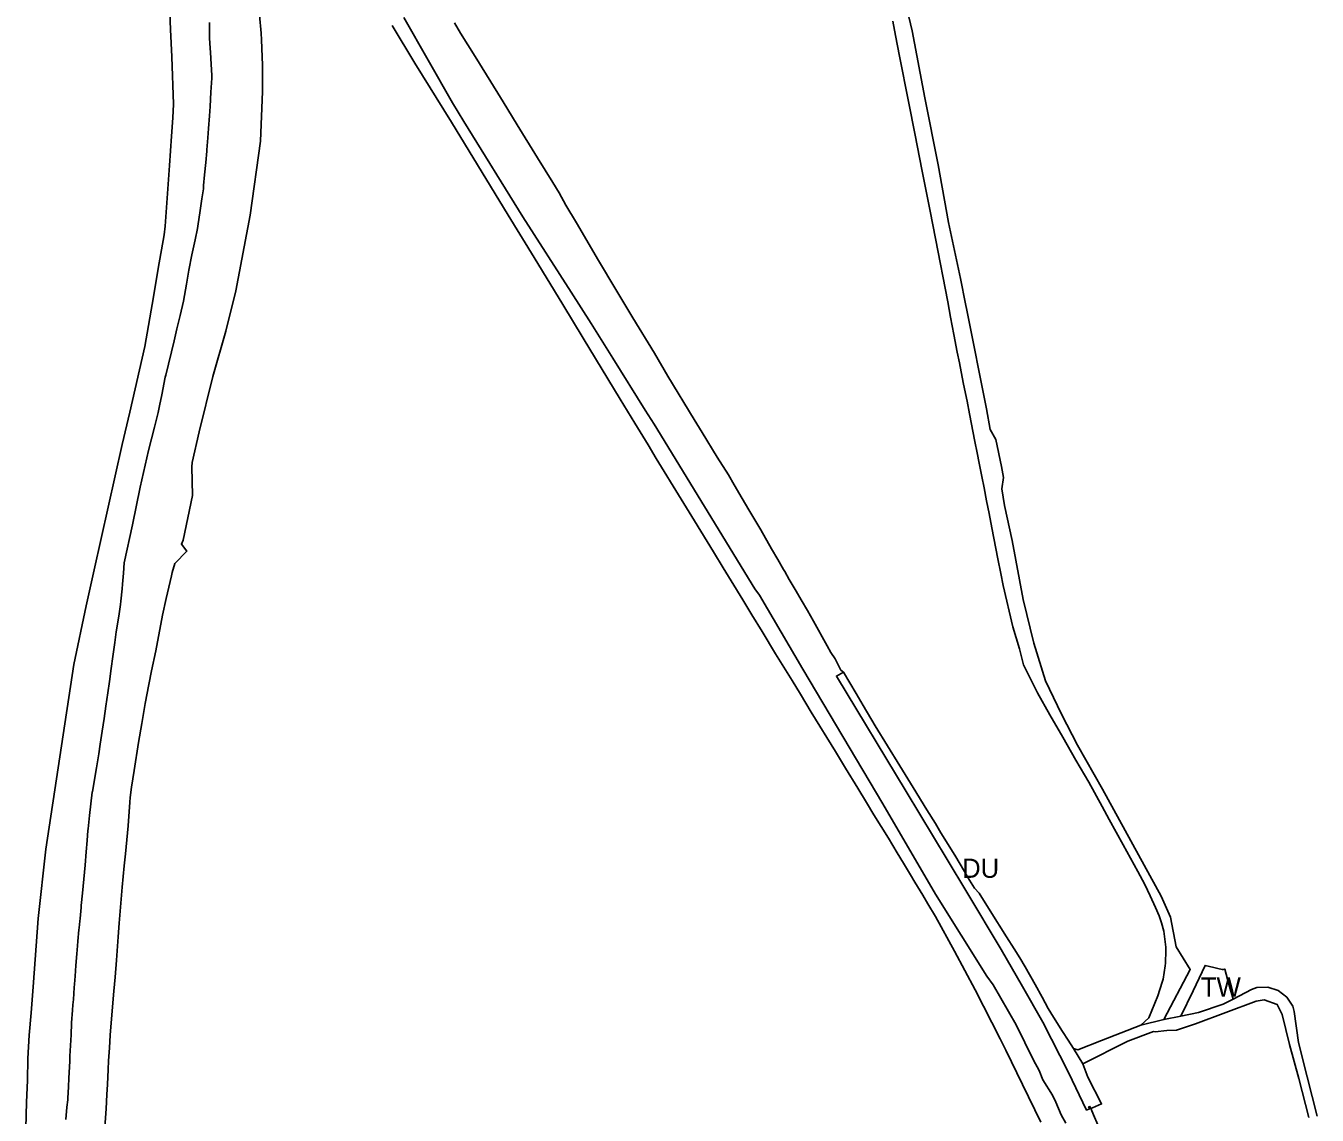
# Model space of a CAD drawing. Extents: x -521047 to -518054, y -1194945 to -1189555.
# Drawn here: x -520853 to -520181, y -1190690 to -1190123 of the extents above; entities that cross this region are included whole.
import ezdxf

# ---------------------------------------------------------------- set-up
doc = ezdxf.new("R2010")
doc.units = 0
for name, color, linetype in [('90310013', 7, 'Continuous'), ('90310023', 7, 'Continuous'), ('90320013', 7, 'Continuous'), ('90390013', 7, 'Continuous')]:
    doc.layers.add(name, color=color, linetype=linetype)

msp = doc.modelspace()

# ---------------------------------------------------------------- linework, layer by layer
at = {"layer": '90310013'}
for points in [[(-520311.54, -1190694.38), (-520313.81, -1190690.05), (-520316.69, -1190683.47), (-520318.39, -1190679.81), (-520323.39, -1190671.81), (-520325.29, -1190666.88), (-520328.39, -1190661.64), (-520337.38, -1190643.13), (-520349.34, -1190622.37), (-520352.61, -1190617.78), (-520379.37, -1190575.04), (-520406.8, -1190528.05), (-520448.49, -1190457.74), (-520471.06, -1190419.32), (-520473.45, -1190415.9), (-520525.96, -1190330.07), (-520530.58, -1190322.93), (-520547.56, -1190295.76), (-520558.81, -1190277.75), (-520569.14, -1190261.44), (-520594.4, -1190222.18), (-520625.12, -1190172.36), (-520630.98, -1190162.68), (-520656.35, -1190118.25)], [(-520662.54, -1190122.49), (-520650.61, -1190142), (-520631.58, -1190172.83), (-520602.03, -1190221.27), (-520588.57, -1190243.38), (-520573.64, -1190267.85), (-520562.95, -1190285.42), (-520543.65, -1190317.19), (-520536, -1190329.69), (-520529.17, -1190340.88), (-520524.85, -1190347.98), (-520511.82, -1190369.31), (-520504.99, -1190380.53), (-520495.11, -1190396.67), (-520489.99, -1190405.05), (-520485.87, -1190411.78), (-520479.82, -1190421.71), (-520475.02, -1190429.58), (-520469.77, -1190438.2), (-520462.71, -1190449.78), (-520454.13, -1190463.8), (-520449.8, -1190470.9), (-520444.12, -1190480.2), (-520431.56, -1190500.75), (-520426.27, -1190509.45), (-520419.93, -1190519.84), (-520415.33, -1190527.35), (-520411.44, -1190533.73), (-520403.94, -1190545.91), (-520399.35, -1190553.5), (-520396.02, -1190558.98), (-520392.43, -1190564.91), (-520390.09, -1190568.79), (-520385.97, -1190575.6), (-520383.32, -1190580.03), (-520379.45, -1190586.67), (-520369.41, -1190604.73), (-520358.66, -1190624.95), (-520345.65, -1190650.45), (-520342.71, -1190656.38), (-520334, -1190674.28), (-520324.46, -1190693.89)], [(-520302.58, -1190663.54), (-520307.46, -1190655.43), (-520310.32, -1190651.11), (-520313.14, -1190646.59), (-520317.05, -1190640.57), (-520319.31, -1190636.97), (-520320.59, -1190634.65), (-520323.87, -1190628.67), (-520327.5, -1190622.06), (-520332.64, -1190612.96), (-520335.39, -1190608.31), (-520338.33, -1190603.61), (-520342.37, -1190597.29), (-520350.92, -1190583.67), (-520356.67, -1190574.53), (-520359.14, -1190572.02), (-520362.5, -1190566.32), (-520364.34, -1190563.2), (-520369.26, -1190554.67), (-520376.52, -1190543.09), (-520379.44, -1190538.17), (-520383.85, -1190531.04), (-520391.01, -1190519.48), (-520397.98, -1190508.23), (-520410.78, -1190487.26), (-520417.03, -1190476.73), (-520420.7, -1190470.58), (-520427.37, -1190459.39), (-520431.02, -1190461.45), (-520394.68, -1190521.61), (-520373.25, -1190557.02), (-520363.08, -1190574.03), (-520345.16, -1190603.9), (-520333.97, -1190623.14), (-520323.53, -1190641.8), (-520310.09, -1190667.94), (-520300.63, -1190687.6), (-520299.19, -1190687), (-520299.58, -1190685.96), (-520298.9, -1190685.67), (-520298.45, -1190686.69), (-520297.57, -1190686.32), (-520292.81, -1190684.4), (-520300.02, -1190670.48), (-520302.58, -1190663.54)], [(-520180.5, -1190690.67), (-520185.7, -1190670.28), (-520190.15, -1190652.41), (-520192.44, -1190636.14), (-520193.15, -1190633.39), (-520196.31, -1190628.66), (-520200.85, -1190625.24), (-520206.24, -1190623.53), (-520211.94, -1190623.66), (-520214.66, -1190624.69), (-520224.31, -1190629.74), (-520229.44, -1190632.43), (-520242.27, -1190636.69), (-520251.47, -1190638.58), (-520260.36, -1190640.4), (-520272.31, -1190643.28), (-520292.86, -1190651.31), (-520305.17, -1190656.12), (-520307.46, -1190655.43), (-520302.58, -1190663.54)], [(-520302.58, -1190663.54), (-520279.12, -1190651.75), (-520265.85, -1190646.71), (-520264.87, -1190646.73), (-520258.89, -1190646.14), (-520253.81, -1190645.91), (-520243.84, -1190642.67), (-520212.3, -1190630.74), (-520208.07, -1190630.09), (-520201.28, -1190632.52), (-520198.74, -1190637.77), (-520194.85, -1190653.37), (-520190.1, -1190671.19), (-520184.89, -1190691.51)]]:
    msp.add_lwpolyline(points, dxfattribs=at)
at = {"layer": '90310023'}
for points in [[(-520778.83, -1190102.4), (-520777.95, -1190124.57), (-520777.29, -1190138.74), (-520776.47, -1190163.36), (-520776.83, -1190170.44), (-520777.49, -1190180.07), (-520778.53, -1190195.44), (-520780.79, -1190226.94), (-520781.3, -1190231.43), (-520784.36, -1190249.11), (-520786.83, -1190263.81), (-520791.44, -1190289.68), (-520799.14, -1190323.82), (-520803.11, -1190340.79), (-520817.75, -1190406.02), (-520822, -1190424.77), (-520828.37, -1190455.3), (-520842.97, -1190551.61), (-520846.95, -1190587.68), (-520849.58, -1190623.3), (-520850.63, -1190636.95), (-520851.64, -1190648.56), (-520852.28, -1190660.73), (-520852.56, -1190672.24), (-520852.94, -1190683.51), (-520853.37, -1190697.08)], [(-520401.68, -1190120.11), (-520400.22, -1190127.57), (-520398.08, -1190138.46), (-520393.44, -1190162.05), (-520389.99, -1190179.56), (-520386.49, -1190197.4), (-520382.22, -1190219.18), (-520379.42, -1190233.48), (-520372.97, -1190266.32), (-520371.58, -1190274.42), (-520369.76, -1190283.42), (-520368, -1190292.59), (-520366.87, -1190298.24), (-520364.88, -1190308.35), (-520363.75, -1190314.16), (-520362.96, -1190318.16), (-520361.67, -1190324.78), (-520358.8, -1190339.19), (-520357.64, -1190345.16), (-520356.65, -1190350.44), (-520356.28, -1190352.2), (-520355.24, -1190357.44), (-520354.1, -1190363.35), (-520352.77, -1190370.15), (-520351.48, -1190376.69), (-520349.98, -1190384.24), (-520346.85, -1190400.25), (-520345.34, -1190407.94), (-520344.11, -1190414.17), (-520339.16, -1190435.68), (-520335.69, -1190447.27), (-520333.6, -1190455.52), (-520326.28, -1190470.19), (-520319.79, -1190481.7), (-520313.06, -1190493.24), (-520306.18, -1190505.19), (-520299.49, -1190516.65), (-520292.56, -1190529.3), (-520288.83, -1190536.11), (-520281.56, -1190549.39), (-520273.96, -1190563.31), (-520270.32, -1190570.06), (-520267.58, -1190575.89), (-520264.82, -1190581.96), (-520262.79, -1190586.33), (-520261.69, -1190589.95), (-520260.46, -1190594.42), (-520260.08, -1190597.14), (-520259.34, -1190602.74), (-520259.34, -1190604.41), (-520259.47, -1190611.1), (-520259.64, -1190612.41), (-520260.77, -1190619.4), (-520261.32, -1190621), (-520263.6, -1190628.04), (-520268.22, -1190639.47), (-520272.31, -1190643.28), (-520260.36, -1190640.4), (-520246.6, -1190614.37), (-520254.03, -1190602.44), (-520256.94, -1190586.97), (-520261.73, -1190576.17), (-520292.37, -1190520.37), (-520305.38, -1190497.4), (-520313.7, -1190481.31), (-520322.01, -1190463.84), (-520328.19, -1190444.19), (-520333.62, -1190421.51), (-520339.48, -1190390.73), (-520343.5, -1190372.52), (-520344.85, -1190363.88), (-520343.97, -1190357.86), (-520345.06, -1190352.29), (-520347.86, -1190338.07), (-520350.9, -1190332.99), (-520352.86, -1190322.18), (-520363.12, -1190270.76), (-520363.78, -1190267.42), (-520366.37, -1190254.23), (-520372.66, -1190225.12), (-520377.99, -1190195.02), (-520384.87, -1190160.07), (-520391.56, -1190125.16), (-520393.2, -1190117.89)], [(-520832.56, -1190692.51), (-520831.92, -1190686.11), (-520831.53, -1190682.22), (-520831.48, -1190681.4), (-520831.18, -1190675.42), (-520830.95, -1190670.95), (-520830.65, -1190664.99), (-520830.5, -1190662.17), (-520830.37, -1190659.51), (-520830.09, -1190653.98), (-520829.81, -1190648.4), (-520829.5, -1190642.29), (-520829.49, -1190642.08), (-520829, -1190635.46), (-520828.79, -1190632.68), (-520828.59, -1190629.93), (-520828.13, -1190623.75), (-520828, -1190622.02), (-520827.69, -1190617.85), (-520827.28, -1190612.32), (-520826.82, -1190606.09), (-520826.51, -1190601.96), (-520826.28, -1190599.56), (-520825.69, -1190593.61), (-520825.59, -1190592.55), (-520825.25, -1190589.08), (-520825.13, -1190587.77), (-520824.56, -1190581.94), (-520824.46, -1190580.91), (-520823.86, -1190574.55), (-520822.46, -1190559.96), (-520821.91, -1190553.06), (-520821.44, -1190547.14), (-520821.02, -1190541.86), (-520820.91, -1190540.94), (-520820.12, -1190534.01), (-520819.44, -1190528.07), (-520818.73, -1190521.84), (-520818.67, -1190521.49), (-520816.62, -1190509.25), (-520815.39, -1190501.97), (-520814.61, -1190496.95), (-520813.56, -1190490.15), (-520812.54, -1190483.57), (-520811.63, -1190477.09), (-520810.65, -1190470.17), (-520809.83, -1190464.32), (-520808.9, -1190457.54), (-520808.05, -1190451.22), (-520807.06, -1190443.91), (-520806.22, -1190438.37), (-520804.98, -1190430.18), (-520804.05, -1190424.07), (-520803.81, -1190422.46), (-520803.25, -1190415.91), (-520803.04, -1190413.49), (-520802.55, -1190407.76), (-520802.08, -1190402.34), (-520797.81, -1190382.66), (-520793.77, -1190363.04), (-520789.51, -1190343.91), (-520786.36, -1190331.78), (-520785.46, -1190328.32), (-520784.38, -1190324.15), (-520783.68, -1190320.65), (-520782.55, -1190314.95), (-520780.71, -1190305.7), (-520780.47, -1190304.54), (-520776.16, -1190286.78), (-520774.67, -1190280.5), (-520773, -1190273.46), (-520771.25, -1190266.04), (-520769.69, -1190257.16), (-520768.43, -1190249.96), (-520766.85, -1190241.85), (-520765.22, -1190234.17), (-520763.96, -1190228.21), (-520763.7, -1190226.98), (-520762.5, -1190218.73), (-520761.63, -1190212.72), (-520760.87, -1190207.48), (-520760.72, -1190205.7), (-520760.23, -1190200.24), (-520759.65, -1190193.81), (-520759.12, -1190187.87), (-520759.06, -1190187.22), (-520758.55, -1190180.97), (-520758.15, -1190176.09), (-520757.6, -1190169.44), (-520757.3, -1190164.53), (-520756.9, -1190157.22), (-520756.5, -1190149.9), (-520756.42, -1190148.49), (-520756.81, -1190142.53), (-520757.19, -1190136.49), (-520757.5, -1190131.72), (-520757.68, -1190128.9), (-520757.7, -1190126.98), (-520757.75, -1190120.86)]]:
    msp.add_lwpolyline(points, dxfattribs=at)
at = {"layer": '90320013'}
for points in [[(-520812.74, -1190703.8), (-520811.58, -1190686.99), (-520811.13, -1190679.39), (-520810.86, -1190674.27), (-520810.49, -1190666.44), (-520810.21, -1190661.95), (-520809.76, -1190655.1), (-520809.38, -1190648.62), (-520808.7, -1190640.05), (-520807.44, -1190625.67), (-520806.79, -1190618.32), (-520806.21, -1190609.49), (-520805.28, -1190597.35), (-520804.73, -1190590.26), (-520803.12, -1190571.38), (-520802.05, -1190560.34), (-520801.46, -1190554.11), (-520800.12, -1190539.43), (-520799.22, -1190527.06), (-520799.02, -1190524.64), (-520798.24, -1190519.38), (-520796.96, -1190510.64), (-520794.61, -1190496.02), (-520792.99, -1190486.07), (-520791.14, -1190475.72), (-520789.3, -1190465.75), (-520787.86, -1190458.71), (-520785.71, -1190448.27), (-520782.1, -1190429.75), (-520780.24, -1190420.99), (-520777.52, -1190409.2), (-520777.17, -1190407.4), (-520775.69, -1190402.84), (-520769.41, -1190396.26), (-520772.33, -1190392.64), (-520771.4, -1190390.62), (-520766.57, -1190367.27), (-520766.88, -1190352.45), (-520766.67, -1190350.13), (-520763.12, -1190334.1), (-520755.95, -1190305.31), (-520749.23, -1190281.66), (-520744.03, -1190260.62), (-520736.44, -1190221.23), (-520731.14, -1190182.68), (-520730.03, -1190156.85), (-520730.06, -1190143.1), (-520730.21, -1190138.71), (-520730.51, -1190129.92), (-520730.74, -1190126.36), (-520731.61, -1190116.98)], [(-520656.35, -1190118.25), (-520630.98, -1190162.68), (-520625.12, -1190172.36), (-520594.4, -1190222.18), (-520569.14, -1190261.44), (-520558.81, -1190277.75), (-520547.56, -1190295.76), (-520530.58, -1190322.93), (-520525.96, -1190330.07), (-520473.45, -1190415.9), (-520471.06, -1190419.32), (-520448.49, -1190457.74), (-520406.8, -1190528.05), (-520379.37, -1190575.04), (-520352.61, -1190617.78), (-520349.34, -1190622.37), (-520337.38, -1190643.13), (-520328.39, -1190661.64), (-520325.29, -1190666.88), (-520323.39, -1190671.81), (-520318.39, -1190679.81), (-520316.69, -1190683.47), (-520313.81, -1190690.05), (-520311.54, -1190694.38)], [(-520757.75, -1190120.86), (-520757.7, -1190126.98), (-520757.68, -1190128.9), (-520757.5, -1190131.72), (-520757.19, -1190136.49), (-520756.81, -1190142.53), (-520756.42, -1190148.49), (-520756.5, -1190149.9), (-520756.9, -1190157.22), (-520757.3, -1190164.53), (-520757.6, -1190169.44), (-520758.15, -1190176.09), (-520758.55, -1190180.97), (-520759.06, -1190187.22), (-520759.12, -1190187.87), (-520759.65, -1190193.81), (-520760.23, -1190200.24), (-520760.72, -1190205.7), (-520760.87, -1190207.48), (-520761.63, -1190212.72), (-520762.5, -1190218.73), (-520763.7, -1190226.98), (-520763.96, -1190228.21), (-520765.22, -1190234.17), (-520766.85, -1190241.85), (-520768.43, -1190249.96), (-520769.69, -1190257.16), (-520771.25, -1190266.04), (-520773, -1190273.46), (-520774.67, -1190280.5), (-520776.16, -1190286.78), (-520780.47, -1190304.54), (-520780.71, -1190305.7), (-520782.55, -1190314.95), (-520783.68, -1190320.65), (-520784.38, -1190324.15), (-520785.46, -1190328.32), (-520786.36, -1190331.78), (-520789.51, -1190343.91), (-520793.77, -1190363.04), (-520797.81, -1190382.66), (-520802.08, -1190402.34), (-520802.55, -1190407.76), (-520803.04, -1190413.49), (-520803.25, -1190415.91), (-520803.81, -1190422.46), (-520804.05, -1190424.07), (-520804.98, -1190430.18), (-520806.22, -1190438.37), (-520807.06, -1190443.91), (-520808.05, -1190451.22), (-520808.9, -1190457.54), (-520809.83, -1190464.32), (-520810.65, -1190470.17), (-520811.63, -1190477.09), (-520812.54, -1190483.57), (-520813.56, -1190490.15), (-520814.61, -1190496.95), (-520815.39, -1190501.97), (-520816.62, -1190509.25), (-520818.67, -1190521.49), (-520818.73, -1190521.84), (-520819.44, -1190528.07), (-520820.12, -1190534.01), (-520820.91, -1190540.94), (-520821.02, -1190541.86), (-520821.44, -1190547.14), (-520821.91, -1190553.06), (-520822.46, -1190559.96), (-520823.86, -1190574.55), (-520824.46, -1190580.91), (-520824.56, -1190581.94), (-520825.13, -1190587.77), (-520825.25, -1190589.08), (-520825.59, -1190592.55), (-520825.69, -1190593.61), (-520826.28, -1190599.56), (-520826.51, -1190601.96), (-520826.82, -1190606.09), (-520827.28, -1190612.32), (-520827.69, -1190617.85), (-520828, -1190622.02), (-520828.13, -1190623.75), (-520828.59, -1190629.93), (-520828.79, -1190632.68), (-520829, -1190635.46), (-520829.49, -1190642.08), (-520829.5, -1190642.29), (-520829.81, -1190648.4), (-520830.09, -1190653.98), (-520830.37, -1190659.51), (-520830.5, -1190662.17), (-520830.65, -1190664.99), (-520830.95, -1190670.95), (-520831.18, -1190675.42), (-520831.48, -1190681.4), (-520831.53, -1190682.22), (-520831.92, -1190686.11), (-520832.56, -1190692.51)], [(-520294.84, -1190695.28), (-520297.09, -1190690.03), (-520298.24, -1190687.15), (-520298.45, -1190686.69), (-520298.9, -1190685.67), (-520299.58, -1190685.96), (-520299.19, -1190687), (-520300.63, -1190687.6), (-520310.09, -1190667.94), (-520323.53, -1190641.8), (-520333.97, -1190623.14), (-520345.16, -1190603.9), (-520363.08, -1190574.03), (-520373.25, -1190557.02), (-520394.68, -1190521.61), (-520431.02, -1190461.45), (-520427.37, -1190459.39), (-520428.66, -1190458.29), (-520431.58, -1190452.47), (-520433.93, -1190449.11), (-520435.78, -1190445.73), (-520442.94, -1190432.82), (-520446.15, -1190427.25), (-520449.33, -1190421.77), (-520452.05, -1190417.09), (-520455.54, -1190411.02), (-520457.88, -1190406.97), (-520458.54, -1190405.84), (-520461.6, -1190400.68), (-520464.79, -1190395.13), (-520470.42, -1190385.29), (-520474.06, -1190379.19), (-520476.65, -1190374.74), (-520480.03, -1190368.97), (-520484.26, -1190361.73), (-520487.23, -1190356.63), (-520493.14, -1190347.28), (-520500.89, -1190334.53), (-520505.06, -1190327.7), (-520518.77, -1190305.18), (-520525.87, -1190293.08), (-520537.12, -1190274.8), (-520546, -1190259.94), (-520555.01, -1190244.86), (-520566.46, -1190225.16), (-520571.92, -1190216.03), (-520575.54, -1190209.65), (-520578.85, -1190204.26), (-520586.78, -1190191.32), (-520597.31, -1190174.18), (-520604.7, -1190162.17), (-520607.45, -1190157.65), (-520619.25, -1190138.59), (-520626.81, -1190126.38), (-520630.08, -1190121.08)]]:
    msp.add_lwpolyline(points, dxfattribs=at)
at = {"layer": '90390013'}
msp.add_lwpolyline([(-520224.31, -1190629.74), (-520226.49, -1190621.92), (-520228.66, -1190614.1), (-520229.32, -1190614.25), (-520229.99, -1190614.4), (-520232.21, -1190613.85), (-520234.43, -1190613.3), (-520238.87, -1190612.21), (-520245.17, -1190625.39), (-520251.47, -1190638.58), (-520242.27, -1190636.69), (-520229.44, -1190632.43), (-520224.31, -1190629.74)], dxfattribs=at)

# ---------------------------------------------------------------- texts
at = {"layer": '90310013'}
msp.add_text('DU', height=10, rotation=360, dxfattribs=at).set_placement((-520365.52, -1190566.56))
at = {"layer": '90390013'}
msp.add_text('TW', height=10, rotation=360, dxfattribs=at).set_placement((-520241.08, -1190628.48))

doc.saveas('drawing.dxf')
